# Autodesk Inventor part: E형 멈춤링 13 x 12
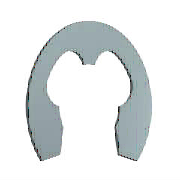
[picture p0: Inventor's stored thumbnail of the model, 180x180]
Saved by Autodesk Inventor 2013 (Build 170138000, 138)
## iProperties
IsCustomPart: 1
Created: 2012-02
Part Number: E형 멈춤링 13 x 12
Material: 강철, 연강
Description: 스프링 리테이닝 링
Document SubType Name: Modeling
Standard: JIS B 2805
Designer: mdu-01
Standards Organization: JIS
Language: ko-KR
Size Designation: 12
Categories: <MemberInstance><Categories><Category DisplayName="샤프트 부품" InternalName="7f7aeb1f-a693-4053-b835-cee3144e0d98" Mnemonic="SHFT"><Category DisplayName="써클립" Inter
Density: 1 g/cm^3
Author: mdu-01
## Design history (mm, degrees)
sketch "스케치1"
  geometry: L1 (-1.2, 0.024)-(0, 0.024) reference; L2 (-3.206, 0)-(3.486, 0) reference; L3 (-5.499, -8.876)-(5.499, -8.876); L4 (0, 1.949)-(0, -3.479) reference; L5 (-7.2, -4.076)-(-6.024, -4.076); L6 (-1.2, 0.724)-(-1.2, 1.889); L7 (0, 5.024)-(2.53, 5.024); L8 (-5.499, -8.876)-(-6.729, -11.985); L9 (0, -0.476)-(-1.278, -0.476); L10 (5.499, -8.876)-(6.729, -11.985); L11 (7.2, -4.076)-(6.024, -4.076); L12 (1.2, 0.724)-(1.2, 1.889); C1 r 6.5 at (0, -6.476); A1 r 6 centre (0, -6.476) between (-5.683, -4.552) and (-5.499, -8.876); A2 r 1.2 centre (0, 0.724) between (-1.2, 0.724) and (1.2, 0.724); A3 r 11.5 centre (0, -6.476) between (9.962, -12.222) and (-9.962, -12.222); A4 r 9.6 centre (0, -6.476) between (-2.4, 2.819) and (-8.471, -1.959); A5 r 0.96 centre (-2.16, 1.889) between (-1.2, 1.889) and (-2.4, 2.819); A6 r 1.44 centre (-7.2, -2.636) between (-8.471, -1.959) and (-7.2, -4.076); A7 r 0.36 centre (-6.024, -4.436) between (-5.683, -4.552) and (-6.024, -4.076); A8 r 1.8 centre (-8.403, -11.323) between (-9.962, -12.222) and (-6.729, -11.985); A9 r 1.8 centre (8.403, -11.323) between (6.729, -11.985) and (9.962, -12.222); A10 r 6 centre (0, -6.476) between (5.499, -8.876) and (5.683, -4.552); A11 r 0.36 centre (6.024, -4.436) between (6.024, -4.076) and (5.683, -4.552); A12 r 1.44 centre (7.2, -2.636) between (7.2, -4.076) and (8.471, -1.959); A13 r 9.6 centre (0, -6.476) between (8.471, -1.959) and (2.4, 2.819); A14 r 0.96 centre (2.16, 1.889) between (2.4, 2.819) and (1.2, 1.889); 1 further point
  constraints: 30 point on circle, 20 end point, 15 centre point, 13 symmetric about line, 12 tangent, 8 point on line, 4 parallel, 2 coincident, 2 horizontal, 1 concentric, 1 perpendicular, 1 vertical alignment, 9 other
  dimensions: "d0" = 13 diameter of C1 (= WD); "d3" = 2.4 distance from line of A1.centre L3 (= 0.2 x ND); "d4" = 1.2 radius of A2 (= 0.1 x ND); "d5" = 23 diameter of A3 (= SD2); "d8" = 9.6 radius of A4 (= 0.8 x ND); "d9" = 2.4 distance from line of A1.centre L5 (= 0.2 x ND); "d10" = 0.96 radius of A5 (= 0.08 x ND); "d11" = 1.44 radius of A6 (= 0.12 x ND); "d12" = 0.36 radius of A7 (= 0.03 x ND); "d13" = 1.8 radius of A8 (= 0.15 x ND); "d14" = 6 distance from line of A1.centre L9 (= 0.5 x ND); "d15" = 6 radius of A1 (= 0.5 x ND)
extrude "본체" new body sketch "스케치1" distance "d16" = 1 (= SD); taper "d17" = 0 deg
workaxis "Work Axis1"
workaxis "Work Axis2"
workplane "Work Plane1"
body "Solid1"
other parameters: "ND" = 12 [user parameter; used in 14 equation terms], "SD" = 1 [user parameter; used in 1 equation term], "WD" = 13 (= WDMIN) [user parameter; used in 1 equation term], "d1" = 19.2 (= 1.6 x ND), "d2" = 12 (= ND), "SD2" = 23 [user parameter; used in 1 equation term], "d6" = 12 (= ND), "d7" = 1.8 (= 0.15 x ND), "d18" = 0, "d19" = 0, "d27" = 0, "d28" = 0, "WDMIN" = 13 [user parameter; used in 1 equation term], "SNB" = 1.15 [user parameter], "WDMAX" = 18 [user parameter], "BUBRMI" = 2.5 [user parameter]
